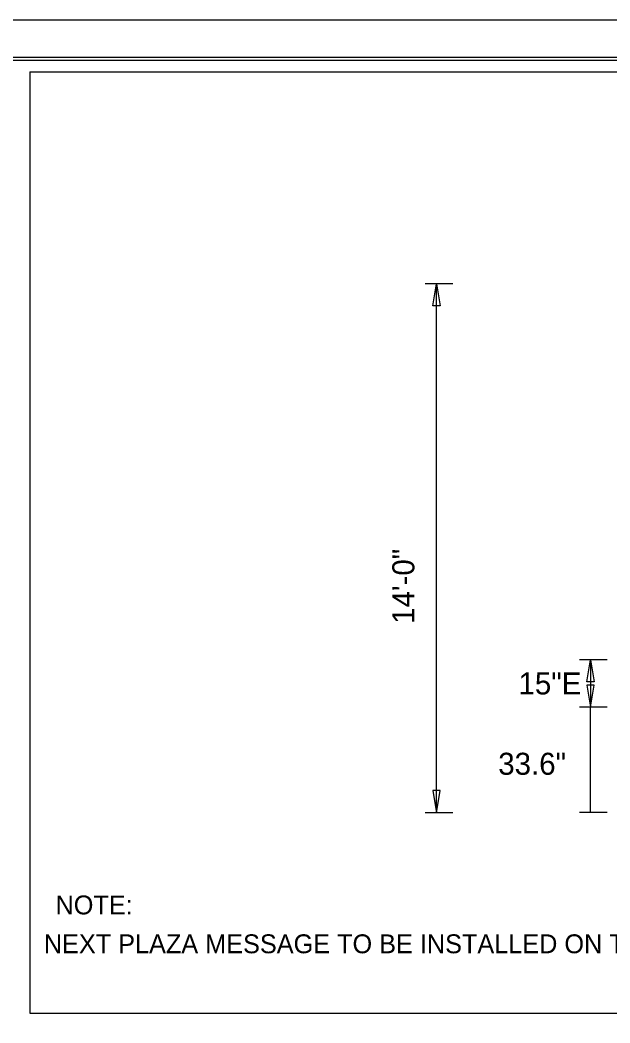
# Model space of a CAD drawing. Extents: x 17890484 to 17890754, y 17897495 to 17897992.
# Drawn here: x 17890512.7 to 17890528.32, y 17897572.31 to 17897598.87 of the extents above; entities that cross this region are included whole.
import ezdxf

# ---------------------------------------------------------------- set-up
doc = ezdxf.new("R2010")
doc.units = 0
for name, color, linetype in [('GSDims', 7, 'Continuous'), ('PlotBorder_dp', 7, 'Continuous'), ('SheetBorder_dp', 7, 'Continuous'), ('SheetLinesMisc2_dp', 7, 'Continuous')]:
    doc.layers.add(name, color=color, linetype=linetype)

msp = doc.modelspace()

# ---------------------------------------------------------------- linework, layer by layer
at = {"layer": 'GSDims'}
for p, q in [((17890524.162, 17897591.883), (17890523.433, 17897591.883)), ((17890523.725, 17897577.881), (17890523.725, 17897591.883)), ((17890528.246, 17897581.928), (17890527.517, 17897581.928)), ((17890528.246, 17897581.928), (17890527.517, 17897581.928)), ((17890527.808, 17897581.928), (17890527.808, 17897580.678)), ((17890528.246, 17897580.678), (17890527.517, 17897580.678)), ((17890528.246, 17897580.678), (17890527.517, 17897580.678)), ((17890527.808, 17897577.883), (17890527.808, 17897580.678)), ((17890524.162, 17897577.881), (17890523.433, 17897577.881)), ((17890528.246, 17897577.883), (17890527.517, 17897577.883))]:
    msp.add_line(p, q, dxfattribs=at)
for points in [[(17890523.725, 17897591.883), (17890523.822, 17897591.299), (17890523.628, 17897591.299)], [(17890527.808, 17897581.928), (17890527.905, 17897581.344), (17890527.711, 17897581.344)], [(17890527.808, 17897580.678), (17890527.905, 17897581.261), (17890527.711, 17897581.261)], [(17890523.725, 17897577.881), (17890523.822, 17897578.464), (17890523.628, 17897578.464)]]:
    msp.add_lwpolyline(points, close=True, dxfattribs=at)
at = {"layer": 'PlotBorder_dp'}
msp.add_lwpolyline([(17890483.9, 17897494.956), (17890645.649, 17897494.956), (17890645.649, 17897598.868), (17890483.9, 17897598.868)], close=True, dxfattribs=at)
at = {"layer": 'SheetBorder_dp'}
msp.add_line((17890489.292, 17897597.887), (17890640.258, 17897597.887), dxfattribs=at)
at = {"layer": 'SheetLinesMisc2_dp'}
for p, q in [((17890489.413, 17897597.808), (17890639.869, 17897597.808)), ((17890512.958, 17897597.496), (17890564.13, 17897597.496)), ((17890512.958, 17897597.496), (17890512.958, 17897572.57)), ((17890512.958, 17897572.57), (17890564.13, 17897572.57))]:
    msp.add_line(p, q, dxfattribs=at)

# ---------------------------------------------------------------- texts
at = {"layer": 'GSDims'}
msp.add_text('14\'-0"', height=0.5833, rotation=90, dxfattribs=at).set_placement((17890523.142, 17897582.881))
for s, height, p in [('15"E', 0.5833, (17890525.9, 17897581.011)), ('33.6"', 0.5833, (17890525.364, 17897578.884)), ('NOTE:', 0.5, (17890513.641, 17897575.188)), ('NEXT PLAZA MESSAGE TO BE INSTALLED ON THE CLOSEST SIGN TO PLAZA ONLY.', 0.5, (17890513.331, 17897574.159))]:
    msp.add_text(s, height=height, dxfattribs=at).set_placement(p)

doc.saveas('drawing.dxf')
